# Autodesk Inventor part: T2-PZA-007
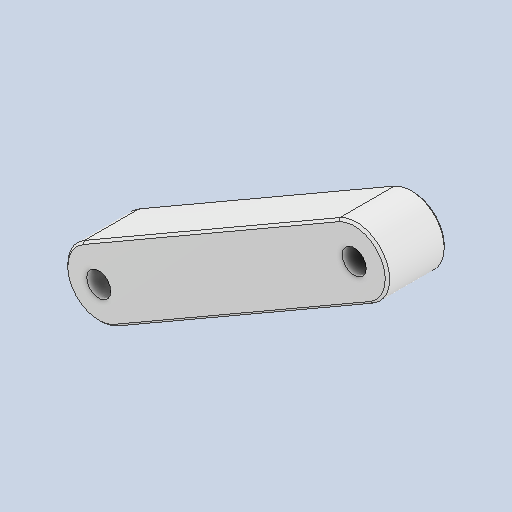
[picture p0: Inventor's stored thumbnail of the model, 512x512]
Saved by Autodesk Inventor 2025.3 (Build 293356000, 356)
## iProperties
Created: 2026-10
Part Number: T2-PZA-007
Material: Genérico
Description: Eslabón exterior
Document SubType Name: Modeling
Designer: Luis MuÃ±oz
Density: 1 g/cm^3
Appearance: Valor por defecto
Project: TESIS 2 - Plataforma mecatrÃ³nica preventiva desacoplada
Sending System: ONSHAPE BY PTC INC, 1.194
Preprocessor: ST-DEVELOPER v20
Material_Fabricacion: PLA
Title: EslabÃ³n exterior
Revision Number: 00
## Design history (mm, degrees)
feature "External_Rod"
node "Sólido1"
